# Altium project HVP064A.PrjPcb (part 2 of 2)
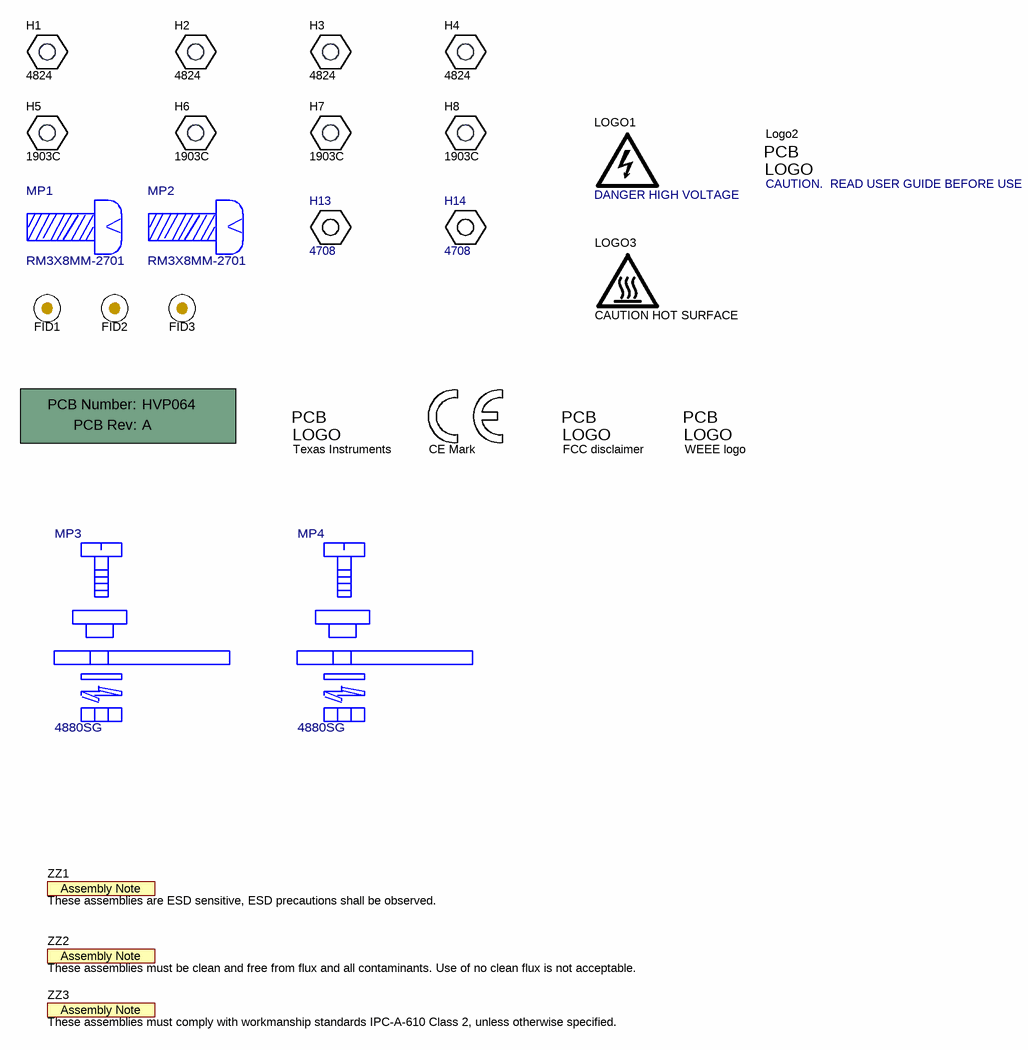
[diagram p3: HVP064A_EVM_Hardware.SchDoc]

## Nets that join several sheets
PGND: HVP064A_PowerStage (17 pins), HVP064A_Control (14 pins)
SGND: HVP064A_PowerStage (33 pins), HVP064A_Control (14 pins)
FB: HVP064A_PowerStage (C24.1 U1.4), HVP064A_Control (U4.5)
HO: HVP064A_PowerStage (D1.1 R1.1), HVP064A_Control (U4.15)
HS: HVP064A_PowerStage (5 pins), HVP064A_Control (C29.2 U4.16)
IN+: HVP064A_PowerStage (13 pins), HVP064A_Control (R42.2)
ISNS: HVP064A_PowerStage (C14.2 C20.1 ISNS.1 R51.2), HVP064A_Control (U4.9)
LO: HVP064A_PowerStage (D4.1 R6.1), HVP064A_Control (U4.11)
Standby_Secondary: HVP064A_PowerStage (Q6.1), HVP064A_Control (R52.1 U6.4)
VCC: HVP064A_PowerStage (5 pins), HVP064A_Control (R25.1 R43.2 U4.12)
VD1: HVP064A_PowerStage (9 pins), HVP064A_Control (R54.2)
VD2: HVP064A_PowerStage (9 pins), HVP064A_Control (R53.1)
VG1: HVP064A_PowerStage (Q4.4), HVP064A_Control (R31.1)
VG2: HVP064A_PowerStage (Q2.4), HVP064A_Control (R32.2)
VIN: HVP064A_PowerStage (6 pins), HVP064A_Control (R29.2)
Vout: HVP064A_PowerStage (6 pins), HVP064A_Control (R24.1 R35.2 R41.2)

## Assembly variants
001: not fitted C2 C19 C23 C27 C28 C34 C35 C37 C38 C42 C43 C44 D6 FID1 FID2 FID3 Q2 Q4 Q6 R2 R7 R20 R24 R31 R32 R35 R41 R42 R44 R48 R50 R52 R53 R54 R55 R56 U3 U5 U6 U7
